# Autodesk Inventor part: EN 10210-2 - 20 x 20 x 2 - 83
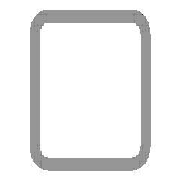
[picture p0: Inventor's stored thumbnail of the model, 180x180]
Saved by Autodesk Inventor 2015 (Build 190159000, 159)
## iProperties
Created: 2015-05
Part Number: EN 10210-2 - 20 x 20 x 2 - 83
Material: Steel, Mild
Description: Tube
Document SubType Name: Modeling
Standard: DIN
Designer: TREINA6
Standard Revision: 1997
Standards Organization: DIN
Language: en-US
Size Designation: 20 x 20 x 2
Categories: <MemberInstance><Categories><Category DisplayName="Structural Shapes" InternalName="089c4875-fa83-4c05-b084-43b9cc11f5ed" Mnemonic="GRDR"><CategoryParameter Dis
Stock Number: 20 x 20 x 2
Density: 7.85 g/cm^3
Appearance: Semi-Polished
IsCustomPart: 1
_CCFamilyMember: 1
_CCFamilyDisplayName: DIN EN 10210-2 (Square) - Tube
_FrameMemberDoc: Frame Member File
_Version: 15.0.0
_GetPNFromCC: 1
Author: TREINA6
G_L: 83,000 mm
G_W: 20,000 mm
G_H: 20,000 mm
+41C98383-8E2D-4390-B5C6-021F51039068+CUTDETAIL1: Cut
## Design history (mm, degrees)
node "Start plane"
node "End plane"
sketch "Sketch"
  geometry: L1 (-10, -7)-(-10, 7); L2 (-7, 10)-(7, 10); L3 (10, 7)-(10, -7); L4 (7, -10)-(-7, -10); L5 (-7, 8)-(7, 8); L6 (8, 7)-(8, -7); L7 (7, -8)-(-7, -8); L8 (-8, -7)-(-8, 7); L9 (0, 14.87)-(0, -14.87) reference; L10 (-14.87, 0)-(14.87, 0) reference; A1 r 3 centre (-7, -7) between (-10, -7) and (-7, -10); A2 r 3 centre (-7, 7) between (-7, 10) and (-10, 7); A3 r 3 centre (7, 7) between (10, 7) and (7, 10); A4 r 3 centre (7, -7) between (7, -10) and (10, -7); A5 r 1 centre (-7, 7) between (-7, 8) and (-8, 7); A6 r 1 centre (7, 7) between (8, 7) and (7, 8); A7 r 1 centre (7, -7) between (7, -8) and (8, -7); A8 r 1 centre (-7, -7) between (-8, -7) and (-7, -8)
  constraints: 16 end point, 16 point on circle, 8 centre point, 8 tangent, 4 parallel, 3 equal radius, 2 perpendicular, 7 other
  dimensions: "d7" = 3 radius of A1 (= G_IR); "d10" = 20 distance between parallel lines of L2 L4 (= G_H); "d11" = 20 distance between parallel lines of L1 L3 (= G_W); "d12" = 2 distance between parallel lines of L3 L6 (= G_T); "d15" = 10 distance between parallel lines of L2 L10 (= 0.5 x d10); "d16" = 10 distance between parallel lines of L9 L3 (= 0.5 x d11)
extrude "Body" new body sketch "Sketch" stored distance "d3" = 83 (= G_L); taper "d4" = 0 deg
node "Driven Length"
  sketch "Sketch3"
    geometry: L1 (0, 0)-(10, 0) reference
    constraints: 2 end point, 1 horizontal
  workplane "Work Plane3"
  sketch "Sketch4"
    geometry: L1 (-2, 0)-(12, 0) reference; L2 (-2, 83)-(12, 83) reference
    dimensions: "d18" = 83 distance between parallel lines of L1 L2 (derived)
workplane "Work Plane4"
split "Split1"
body "Solid1"
other parameters: "G_W" = 20 [user parameter; used in 1 equation term], "G_H" = 20 [user parameter; used in 1 equation term], "G_T" = 2 [user parameter; used in 1 equation term], "G_IR" = 3 [user parameter; used in 1 equation term], "G_L" = 83 (= d18) [user parameter; used in 1 equation term], "G_OFFSET_START" = 0 [user parameter; used in 1 equation term], "d13" = 0 (computed from G_OFFSET_START), "d14" = 83 (= G_OFFSET_END + B_L), "B_L" = 103 [user parameter; used in 1 equation term], "d17" = 90 deg
